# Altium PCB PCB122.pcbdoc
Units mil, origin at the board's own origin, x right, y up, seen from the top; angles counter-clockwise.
Board outline 8605 x 5800 mil, 2 copper layers (Top Layer, Bottom Layer); 37 components, 55 nets, 176 pads, 98 vias.
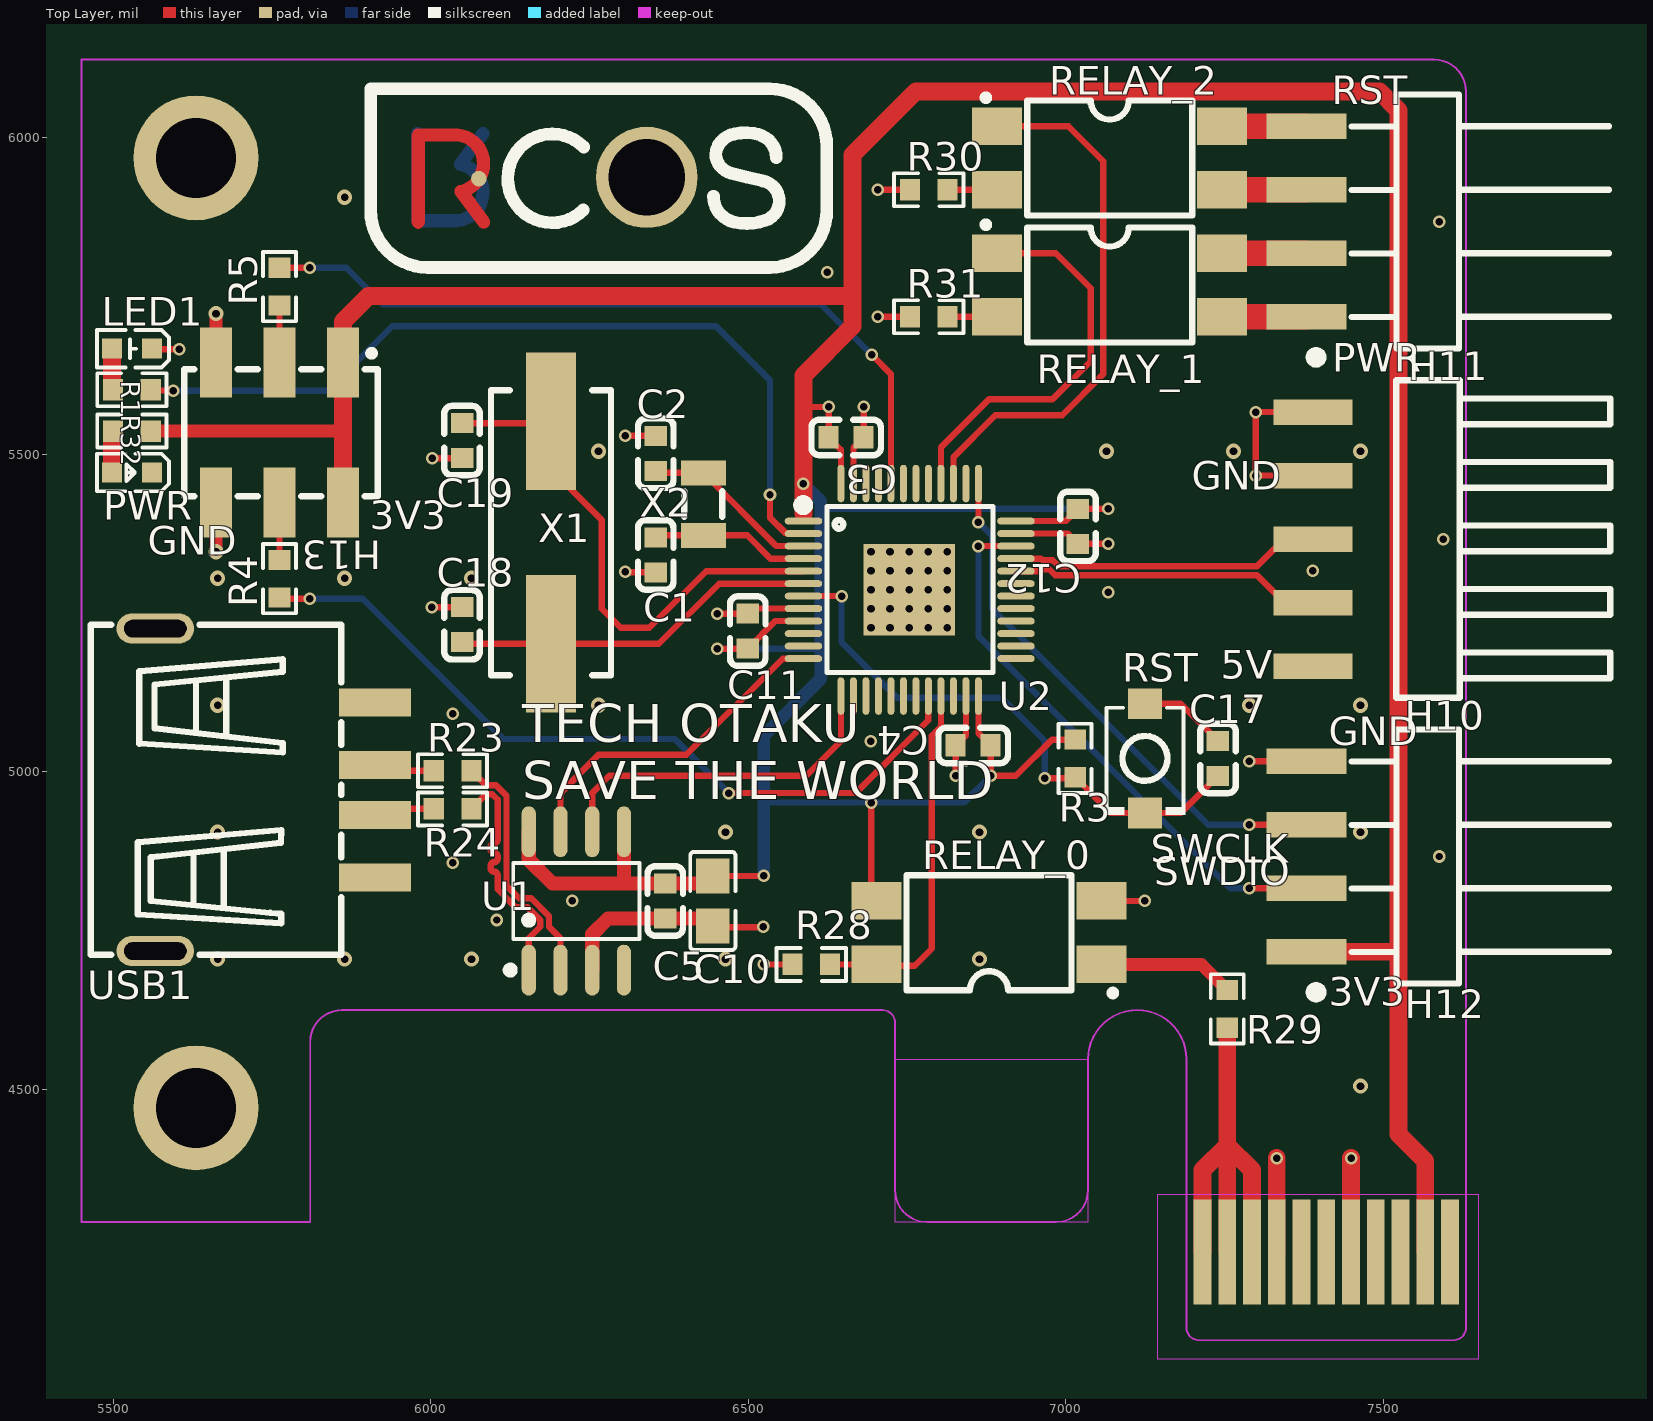
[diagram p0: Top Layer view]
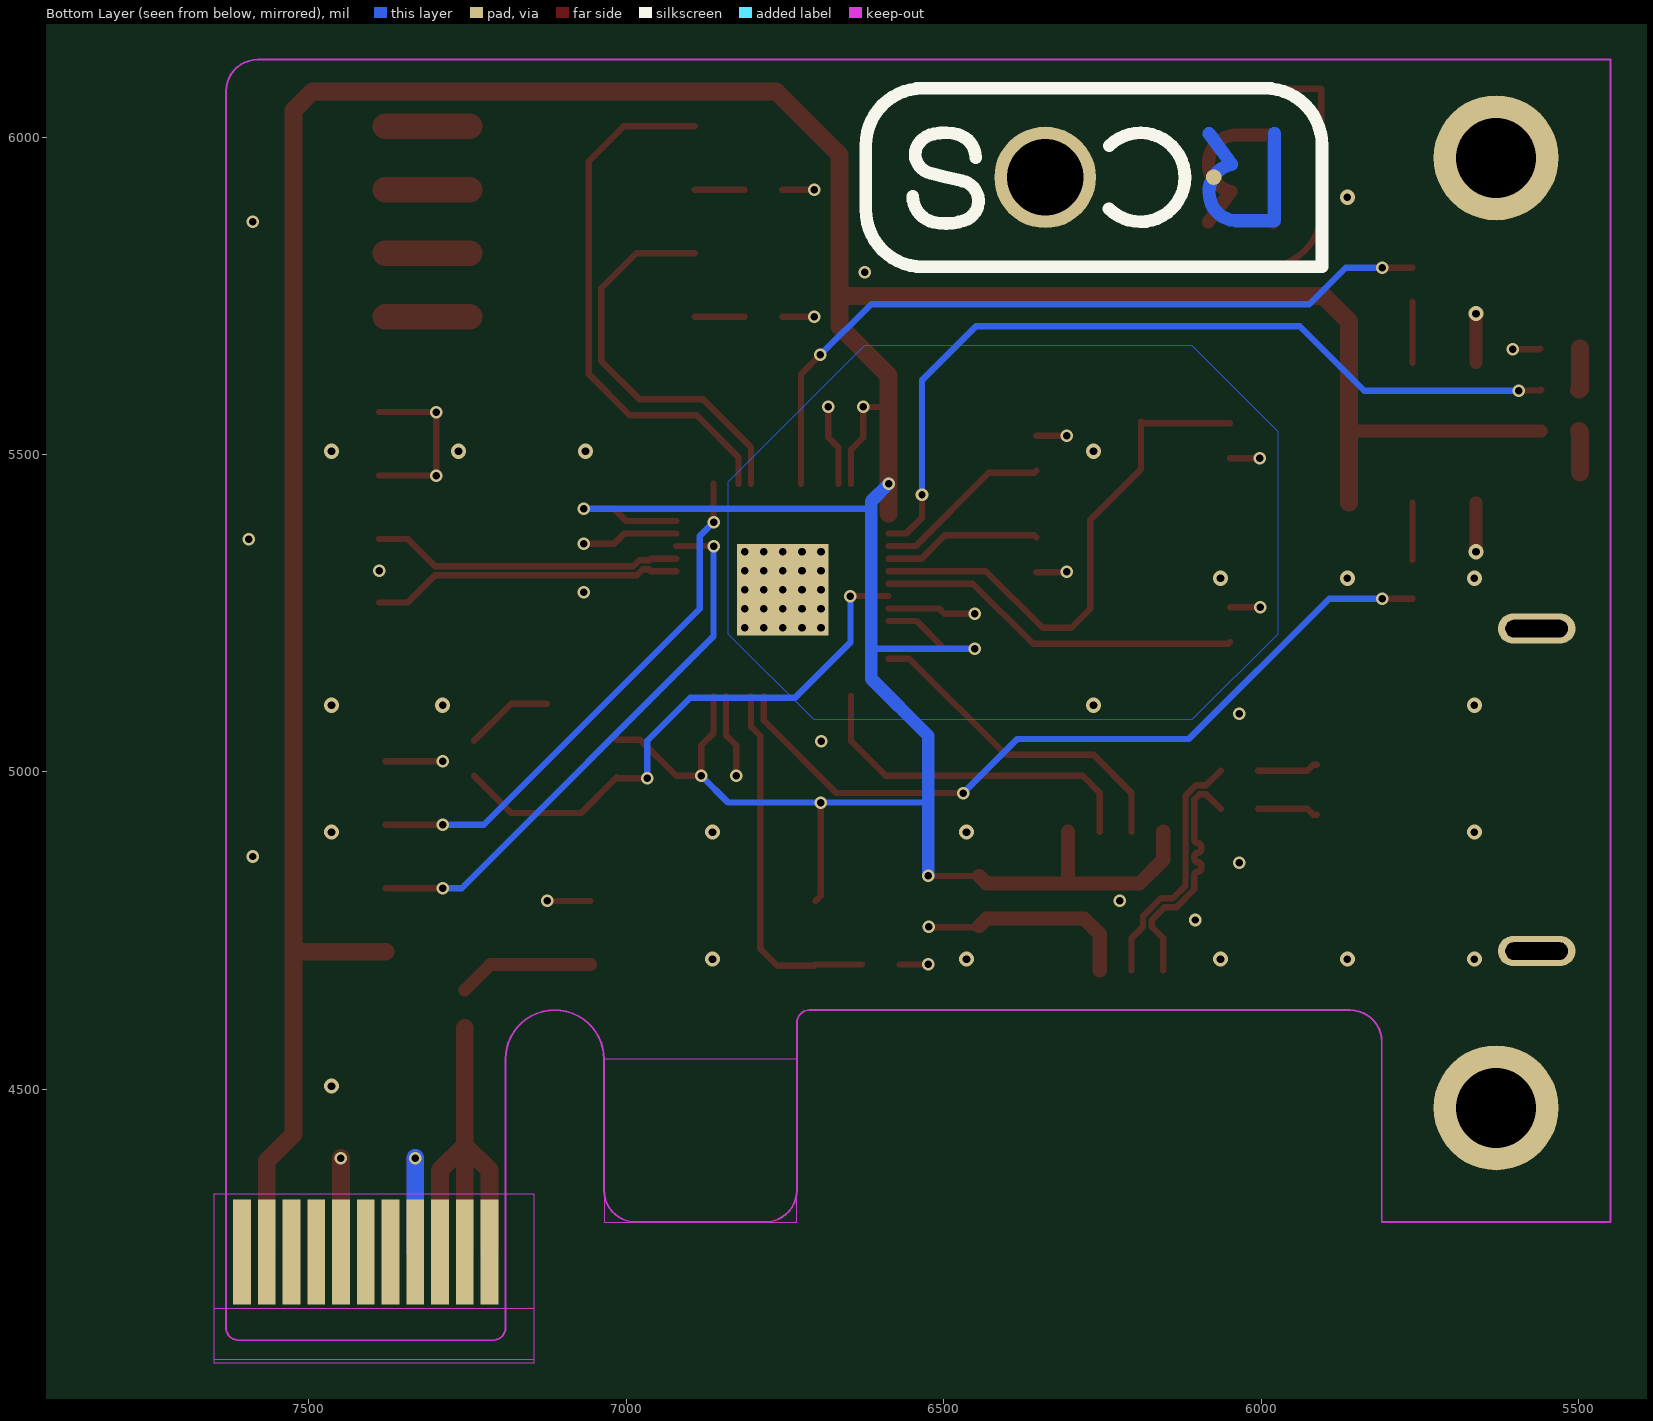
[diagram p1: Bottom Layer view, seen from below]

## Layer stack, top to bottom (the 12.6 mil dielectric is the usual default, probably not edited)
Top Layer: signal copper (thickness not stored)
Dielectric: dielectric 12.6, FR-4, Dk 4.8
Bottom Layer: signal copper (thickness not stored)

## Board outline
11355,2750 2750,2750 2750,8550 11355,8550

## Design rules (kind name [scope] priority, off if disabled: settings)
BoardOutlineClearance copperThickness1oz [All] p0: genericclearance=10 ignorepadtopadclearanceinfootprint=FALSE except(0: Arc-SplitContinuation Track-SplitContinuation SMDPad-SplitContinuation THPad-SplitContinuation Via-SplitContinuation Fill-SplitContinuation Poly-SplitContinuation Region-SplitContinuation Text-SplitContinuation; 6: SMDPad-CutoutEdge THPad-CutoutEdge Via-CutoutEdge Fill-CutoutEdge Region-CutoutEdge; 11: Track-OutlineEdge SMDPad-OutlineEdge THPad-OutlineEdge Via-OutlineEdge Fill-OutlineEdge Region-OutlineEdge Poly-OutlineEdge Text-OutlineEdge; 11.8: Track-CutoutEdge)
BoardOutlineClearance copperThickness2oz [All] p0: genericclearance=10 ignorepadtopadclearanceinfootprint=FALSE except(0: Arc-SplitContinuation Track-SplitContinuation SMDPad-SplitContinuation THPad-SplitContinuation Via-SplitContinuation Fill-SplitContinuation Poly-SplitContinuation Region-SplitContinuation Text-SplitContinuation; 6: SMDPad-CutoutEdge THPad-CutoutEdge Via-CutoutEdge Fill-CutoutEdge Region-CutoutEdge; 11.8: Track-OutlineEdge SMDPad-OutlineEdge THPad-OutlineEdge Via-OutlineEdge Fill-OutlineEdge Region-OutlineEdge Poly-OutlineEdge Text-OutlineEdge Track-CutoutEdge)
Clearance copperThickness1oz [(InNet('OSC32_OUT') OR InNet('GND') OR InNet('OSC32_IN') OR InNet('NRST') OR InNet('$1N1780') OR InNet('SWDIO') OR InNet('SWCLK') OR InNet('PA0') OR InNet('PA4') OR InNet('PA5') OR InNet('PA6') OR InNet('PA7') OR InNet('PB0') OR InNet('PB1') OR InNet('PB10') OR InNet('PB11') OR InNet('PB9') OR InNet('PB8') OR InNet('PB7') OR InNet('PB6') OR InNet('PB5') OR InNet('PB4') OR InNet('PB3') OR InNet('PA15') OR InNet('PA8') OR InNet('PB15') OR InNet('PB14') OR InNet('PB13') OR InNet('PB12') OR InNet('BOOT1') OR InNet('BOOT0') OR InNet('D-') OR InNet('DN') OR InNet('D+') OR InNet('DP') OR InNet('USBDM') OR InNet('USBDP') OR InNet('12V') OR InNet('3V3') OR InNet('UART2_RX') OR InNet('UART2_TX') OR InNet('RST_SW2') OR InNet('RST_SW1') OR InNet('PWR_SW2') OR InNet('PWR_SW1') OR InNet('$1N3179') OR InNet('$1N4269') OR InNet('$1N1798') OR InNet('$1N5301') OR InNet('$1N5302') OR InNet('OSC8_OUT') OR InNet('OSC8_IN') OR InNet('USE_LED') OR InNet('$1N5303') OR InNet('$1N7721'))] p1: gap=7 ignorepadtopadclearanceinfootprint=FALSE except(4: Track-Track; 6: Track-SMDPad SMDPad-SMDPad Track-THPad SMDPad-THPad THPad-THPad Track-Via SMDPad-Via THPad-Via Via-Via Track-Fill SMDPad-Fill THPad-Fill Via-Fill Fill-Fill SMDPad-Region THPad-Region Via-Region Fill-Region Region-Region Track-Poly SMDPad-Poly THPad-Poly Via-Poly Fill-Poly Poly-Poly Track-Text SMDPad-Text THPad-Text Via-Text Fill-Text Region-Text Poly-Text Text-Text; 6.9: Track-Hole SMDPad-Hole THPad-Hole Via-Hole Fill-Hole Region-Hole Poly-Hole Text-Hole Sheet-Hole; 11: Track-Sheet SMDPad-Sheet THPad-Sheet Via-Sheet Fill-Sheet Region-Sheet Poly-Sheet Text-Sheet; 11.8: Track-Region Region-Poly)
Clearance copperThickness2oz [All] p1: gap=7 ignorepadtopadclearanceinfootprint=FALSE except(6: Track-SMDPad SMDPad-SMDPad Track-THPad SMDPad-THPad THPad-THPad Track-Via SMDPad-Via THPad-Via Via-Via Track-Fill SMDPad-Fill THPad-Fill Via-Fill Fill-Fill SMDPad-Region THPad-Region Via-Region Fill-Region Region-Region Track-Poly SMDPad-Poly THPad-Poly Via-Poly Fill-Poly Poly-Poly Track-Text SMDPad-Text THPad-Text Via-Text Fill-Text Region-Text Poly-Text Text-Text; 6.9: Track-Hole SMDPad-Hole THPad-Hole Via-Hole Fill-Hole Region-Hole Poly-Hole Text-Hole Sheet-Hole; 8: Track-Track; 11.8: Track-Region Region-Poly Track-Sheet SMDPad-Sheet THPad-Sheet Via-Sheet Fill-Sheet Region-Sheet Poly-Sheet Text-Sheet)
DiffPairsRouting differentialPair [All] p1: maxuncoupledlength=10 minlimit=4 maxlimit=4 mostfreqgap=4 toplayer_minwidth=5 toplayer_prefwidth=10 toplayer_maxwidth=100 bottomlayer_minwidth=5 bottomlayer_prefwidth=10 bottomlayer_maxwidth=100
PasteMaskExpansion pasteMaskExpansion [All] p1: expansion=0
PlaneConnect innerPlane [All] p1: planeconnectstyle=Relief reliefexpansion=20 reliefentries=4 reliefconductorwidth=10 reliefairgap=10
PolygonConnect copperRegion [All] p1: connectstyle=Direct reliefentries=4 reliefconductorwidth=10 polygonreliefangle="90 Angle" airgapwidth=10
RoutingVias viaSize [All] p1: viastyle="Through Hole" holewidth=12 minholewidth=11.8 maxholewidth=248 width=24 minwidth=19.7 maxwidth=393.7
SolderMaskExpansion solderMaskExpansion [All] p1: useseparateexpansions=TRUE expansion=2 expansionbottom=2
Width copperThickness1oz [All] p1: maxlimit=100 minlimit=5 preferedwidth=10
Width copperThickness2oz [All] p1: maxlimit=100 minlimit=8 preferedwidth=10

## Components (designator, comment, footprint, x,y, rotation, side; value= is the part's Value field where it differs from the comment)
C1 "CL10C220JB8NNNC" C0603 6354.42,5341.92 r90 top
C2 "CL10C220JB8NNNC" C0603 6354.42,5501.92 r270 top
C3 "CGA0603X7R104K500JT" C0603 6654.42,5526.92 r180 top
C4 "CGA0603X7R104K500JT" C0603 6854.42,5041.92 r180 top
C5 "CGA0603X7R104K500JT" C0603 6369.42,4796.92 r90 top
C10 "CL21A106KAYNNNE_C15850" C0805 6444.42,4796.92 r90 top
C11 "CGA0603X7R104K500JT" C0603 6499.42,5221.92 r90 top
C12 "CGA0603X7R104K500JT" C0603 7019.42,5386.92 r270 top
C17 "CGA0603X7R104K500JT" C0603 7239.95,5021.39 r270 top
C18 "CL10C220JB8NNNC" C0603 6049.42,5231.92 r270 top
C19 "CL10C220JB8NNNC" C0603 6049.42,5521.92 r90 top
H10 "HX PZ2.54-1x5P WT" HDR-SMD_5P-P2.54-H-M-W12.8-N 7389.42,5366.92 r90 top
H11 "HX PZ2.54-1x4P WT" CONN-SMD_HX-PZ2.54-1X4P-WT 7379.42,5866.92 r90 top
H12 "HX PZ2.54-1x4P WT" CONN-SMD_HX-PZ2.54-1X4P-WT 7379.42,4866.92 r90 top
H13 "X6521WVS-2x03H-C60D74" HDR-SMD_6P-P2.54-V-M-R2-C5-S7.4 5761.92,5534.42 r180 top
LED1 "NCD0603G1" LED0603-RD_1 5529.42,5666.92 r180 top
PWR "XL-1608SURC-06" LED0603-RD_RED 5529.42,5471.92 r180 top
R1 "0603WAF1001T5E" R0603 5529.42,5601.92 r180 top
R3 "0603WAF1002T5E" R0603 7014.95,5021.39 r90 top
R4 "0603WAF1002T5E" R0603 5761.92,5304.42 r90 top
R5 "0603WAF1002T5E" R0603 5761.92,5764.42 r90 top
R23 "0603WAF220JT5E" R0603 6034.42,5001.92 r0 top
R24 "0603WAF220JT5E" R0603 6034.42,4941.92 r0 top
R28 "0603WAF1002T5E" R0603 6599.42,4696.92 r0 top
R29 "0603WAF2201T5E" R0603 7254.42,4626.92 r270 top
R30 "0603WAF4700T5E" R0603 6784.42,5916.92 r0 top
R31 "0603WAF4700T5E" R0603 6784.42,5716.92 r0 top
R32 "0603WAF1001T5E" R0603 5529.42,5536.92 r180 top
RELAY_0 "G3VM-61D1(TR)" SMD-4_L4.6-W6.4-P2.54-LS10.0-BL 6879.42,4746.92 r90 top
RELAY_1 "G3VM-61D1(TR)" SMD-4_L4.6-W6.4-P2.54-LS10.0-BL 7069.42,5766.92 r270 top
RELAY_2 "G3VM-61D1(TR)" SMD-4_L4.6-W6.4-P2.54-LS10.0-BL 7069.42,5966.92 r270 top
RST "TS-1088-AR02016" SW-SMD_L3.9-W3.0-P4.45 7124.95,5021.39 r270 top
U1 "CH340N_C506813" SOP-8_L5.0-W4.0-P1.27-LS6.0-BL 6229.42,4796.92 r0 top
U2 "STM32F103C8T6" STM32F103C8T6 6754.42,5286.92 r270 top
USB1 "10.0 QHHTZB6.3" USB-A-TH_10.0QHHTZB6.3 5739.42,4971.92 r270 top
X1 "X49SM8MSD2SC" CRYSTAL-SMD_L11.5-W4.8-LS12.7 6189.42,5376.92 r90 top
X2 "Q13FC13500004_C32346" FC-135R_L3.2-W1.5 6429.42,5421.92 r90 top

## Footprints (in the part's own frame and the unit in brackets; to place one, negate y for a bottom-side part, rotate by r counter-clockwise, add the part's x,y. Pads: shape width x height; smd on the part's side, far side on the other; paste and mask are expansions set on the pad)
C0603 [mm]
  rect 0.8x0.9 smd: 1(-0.7,0) 2(0.7,0)
  silkscreen extent -1.39,-0.71 1.39,0.71
C0805 [mm]
  rect 1.41x1.35 smd: 1(-1,0) 2(1,0)
  silkscreen extent -1.96,-0.9 1.96,0.9
CONN-SMD_HX-PZ2.54-1X4P-WT [mm]
  rect 1.02x3.2 smd: 1(-3.81,0) 2(-1.27,0) 3(1.27,0) 4(3.81,0)
  silkscreen extent -5.84,-12.1 5.08,0.03
CRYSTAL-SMD_L11.5-W4.8-LS12.7 [mm]
  rect 5.5x2 smd: 1(-4.45,0) 2(4.45,0)
  silkscreen extent -5.7,-2.4 5.7,2.4
FC-135R_L3.2-W1.5 [mm]
  rect 1x1.8 smd: 1(-1.25,0) 2(1.25,0)
  silkscreen extent -0.51,-0.76 0.51,0.76
HDR-SMD_5P-P2.54-H-M-W12.8-N [mm]
  rect 1.02x3.17 smd: 1(-5.08,0) 2(-2.54,0) 3(0,0) 4(2.54,0) 5(5.08,0)
  silkscreen extent -6.35,-11.9 6.35,-3.33
HDR-SMD_6P-P2.54-V-M-R2-C5-S7.4 [mm]
  rect 1.27x2.8 smd: 1(-2.54,-2.8) 2(-2.54,2.8) 3(0,-2.8) 4(0,2.8) 5(2.54,-2.8) 6(2.54,2.8)
  silkscreen extent -3.94,-3.3 3.81,2.54
LED0603-RD_1 [mm]
  rect 0.8x0.8 smd: 1(-0.799,-0.004) 2(0.799,0.004)
  silkscreen extent -1.49,-0.75 1.39,0.76
LED0603-RD_RED [mm]
  rect 0.8x0.8 smd: 1(-0.8,-0.003) 2(0.8,0.003)
  silkscreen extent -1.49,-0.75 1.39,0.76
R0603 [mil]
  rect 31.75x34.02 smd: 1(-29.66,0) 2(29.66,0)
  silkscreen extent -55,-26 55,26
SMD-4_L4.6-W6.4-P2.54-LS10.0-BL [mm]
  rect 1.5x2 smd: 1(-1.27,-4.5) 2(1.27,-4.5) 3(1.27,4.5) 4(-1.27,4.5)
  silkscreen extent -2.54,-5.08 2.3,3.3
SOP-8_L5.0-W4.0-P1.27-LS6.0-BL [mil]
  oval 22.6x80.14 smd: 1(-75,-108.97) 2(-25,-108.97) 3(25,-108.97) 4(75,-108.97) 5(75,108.97) 6(25,108.97) 7(-25,108.97) 8(-75,108.97)
  silkscreen extent -110,-115 99,60
STM32F103C8T6 [mil]
  oval 10.6x59.1 smd: 1(-108.3,-167.3) 2(-88.6,-167.3) 3(-68.9,-167.3) 4(-49.2,-167.3) 5(-29.5,-167.3) 6(-9.8,-167.3) 7(9.8,-167.3) 8(29.5,-167.3) 9(49.2,-167.3) 10(68.9,-167.3) 11(88.6,-167.3) 12(108.3,-167.3) 25(108.3,167.3) 26(88.6,167.3) 27(68.9,167.3) 28(49.2,167.3) 29(29.5,167.3) 30(9.8,167.3) 31(-9.8,167.3) 32(-29.5,167.3) 33(-49.2,167.3) 34(-68.9,167.3) 35(-88.6,167.3) 36(-108.3,167.3)
  oval 59.1x10.6 smd: 13(167.3,-108.3) 14(167.3,-88.6) 15(167.3,-68.9) 16(167.3,-49.2) 17(167.3,-29.5) 18(167.3,-9.8) 19(167.3,9.8) 20(167.3,29.5) 21(167.3,49.2) 22(167.3,68.9) 23(167.3,88.6) 24(167.3,108.3) 37(-167.3,108.3) 38(-167.3,88.6) 39(-167.3,68.9) 40(-167.3,49.2) 41(-167.3,29.5) 42(-167.3,9.8) 43(-167.3,-9.8) 44(-167.3,-29.5) 45(-167.3,-49.2) 46(-167.3,-68.9) 47(-167.3,-88.6) 48(-167.3,-108.3)
  silkscreen extent -141,-176 130,132
SW-SMD_L3.9-W3.0-P4.45 [mm]
  rect 1.23x1.36 smd: 1(-2.185,0) 2(2.185,0)
  silkscreen extent -2.03,-1.62 2.25,1.62
USB-A-TH_10.0QHHTZB6.3 [mm]
  rect 1.12x2.88 smd: 1(-3.5,4.395) 2(-1,4.395) 3(1,4.395) 4(3.5,4.395)
  oval 1.2x3.1 hole 0.7 slot 2.5 at 90 deg: 5(-6.45,-4.395) 6(6.45,-4.395)
  silkscreen extent -6.6,-6.99 6.6,3.05

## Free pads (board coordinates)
  round 196.85 hole 125.98: 1(5630.3,4471.2) 2(5630.29,5967.27)
  round 160 hole 120: 1(6340.42,5936.54)
  round 24.6 smd far side: 2(6074.93,5936.96)
  round 24.6 smd: 2(6075.93,5934.5)
  rect 144x144 smd far side: 2(6753.44,5286.92)
  rect 144x144 smd: 2(6753.44,5286.92)
  rect 28x165 smd far side: A1(7215.45,4244) A2(7254.45,4244) A3(7293.45,4244) A4(7332.45,4244) A5(7371.45,4244) A6(7410.45,4244) A7(7449.45,4244) A8(7488.45,4244) A9(7527.45,4244) A10(7566.45,4244) A11(7605.45,4244)
  rect 28x165 smd: B1(7215.45,4244) B2(7254.45,4244) B3(7293.45,4244) B4(7332.45,4244) B5(7371.45,4244) B6(7410.45,4244) B7(7449.45,4244) B8(7488.45,4244) B9(7527.45,4244) B10(7566.45,4244) B11(7605.45,4244)

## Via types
v1: diameter 19.7, hole 11.8, Top Layer to Bottom Layer, 49 vias
v2: diameter 24, hole 12, Top Layer to Bottom Layer, 49 vias

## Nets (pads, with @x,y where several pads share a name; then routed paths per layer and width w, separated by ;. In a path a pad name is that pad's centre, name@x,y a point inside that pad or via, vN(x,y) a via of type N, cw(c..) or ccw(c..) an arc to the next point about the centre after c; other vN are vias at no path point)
3V3: C3.2 C4.1 C5.2 C10.2 C11.1 C12.1 H12.1 H13.1 H13.2 pad.B10 R3.2 R32.1 RELAY_0.3 U1.5 U1.8 U2.1 U2.9 U2.24 U2.36 U2.48 | length 7973
  Top Layer w10: C10.2 6523.79,4836.29 v1(6524.42,4836.92) ; v1(6451.42,5194.36) C11.1 6542.78,5237.72 U2.9 ; 6587.12,5574.99 6587.2,5574.92 v1(6626.86,5574.92) C3.2 6646.12,5507.66 U2.48 ; v1(6693.86,4951.92) 6693.86,4805.31 RELAY_0.3 ; U2.24 6862.72,5061.18 C4.1 v1(6881.98,4993.92) 6921.42,4993.92 6978.55,5051.05 R3.2 ; U2.36 7000.16,5395.22 C12.1 v1(7067.42,5414.48)
  Top Layer w20: R32.1 5861.04,5536.92 5861.92,5537.8
  Top Layer w22.6: U1.8 6154.42,4861.92 6191.86,4824.48 C5.2 6432.61,4824.48 C10.2 ; 6304.42,4824.95 U1.5
  Top Layer w28: H13.2 5861.92,5537.8 H13.1 5861.92,5709.42 5902.12,5749.62 6663.74,5749.62 ; 6587.12,5406.92 v1(6587.12,5453.78) 6587.12,5624.62 6664.42,5701.92 6664.42,5971.92 6764.42,6071.92 7494.42,6071.92 7524.42,6041.92 7524.42,4429.55 7566.45,4387.52 pad.B10 ; H12.1 7521.15,4716.62
  Bottom Layer w10: v1(6451.42,5194.36) 6614.35,5194.36 6614.42,5194.29 ; 6524.42,4949.59 6526.75,4951.92 v1(6693.86,4951.92) 6839.98,4951.92 v1(6881.98,4993.92) ; 6614.42,5416.08 6616.02,5414.48 v1(7067.42,5414.48)
  Bottom Layer w20: v1(6524.42,4836.92) 6524.42,5056.92 6614.42,5146.92 6614.42,5416.08 6614.42,5426.48 v1(6587.12,5453.78)
12V: pad.B1 pad.B2 pad.B3 R29.2 | length 722
  Top Layer w28: pad.B1 7215.45,4373.23 7254.45,4412.23 ; pad.B2 7254.45,4412.23 ; R29.2@7254.45,4597.23 7254.45,4412.23 ; pad.B3 7293.45,4373.23 7254.45,4412.23
$1N1780: H13.4 R4.2 | length 90.1
  Top Layer w10: R4.2 H13.4
$1N1798: U2.11
$1N3179: H13.3 R5.1 | length 95.1
  Top Layer w10: H13.3 R5.1@5761.92,5739.76
$1N4269: LED1.2 R1.2 | length 65.6
  Top Layer w28: LED1.2 5497.94,5603.73 R1.2
$1N5301: R30.2 RELAY_2.2 | length 78.2
  Top Layer w10: R30.2 RELAY_2.2
$1N5302: R31.2 RELAY_1.2 | length 78.2
  Top Layer w10: R31.2 RELAY_1.2
$1N5303: R29.1 RELAY_0.1 | length 214.5
  Top Layer w20: RELAY_0.1 7214.08,4696.92 R29.1
$1N7721: PWR.2 R32.2 | length 65.9
  Top Layer w28: PWR.2 5497.94,5535.1 R32.2
BOOT0: R5.2 U2.44 | length 1204.6
  Top Layer w10: R5.2 v1(5809.92,5794.08) ; v1(6694.42,5656.92) 6724.92,5626.42 U2.44
  Bottom Layer w10: v1(5809.92,5794.08) 5867.26,5794.08 5924.42,5736.92 6614.42,5736.92 v1(6694.42,5656.92)
BOOT1: R4.1 U2.20 | length 1234.5
  Top Layer w10: R4.1@5761.92,5273.12 v1(5809.92,5273.12) ; v1(6469.42,4966.92) 6669.42,4966.92 6783.92,5081.42 U2.20
  Bottom Layer w10: v1(5809.92,5273.12) 5893.22,5273.12 6114.42,5051.92 6384.42,5051.92 v1(6469.42,4966.92)
D+: R24.2 U1.1 | length 394.3
  Top Layer w10: R24.2 6087.08,4964.92 6097.08,4964.92 6105.42,4956.58 6105.42,4893.46 cw(c6099.92,4893.46) 6099.92,4887.96 ccw(c6099.92,4882.46) 6094.42,4882.46 6094.42,4878.46 ccw(c6099.92,4878.46) 6099.92,4872.96 cw(c6099.92,4867.46) 6105.42,4867.46 6105.42,4863.46 cw(c6099.92,4863.46) 6099.92,4857.96 ccw(c6099.92,4852.46) 6094.42,4852.46 6094.42,4848.46 ccw(c6099.92,4848.46) 6099.92,4842.96 cw(c6099.92,4837.46) 6105.42,4837.46 6105.42,4815.12 6133.62,4786.92 6152.42,4786.92 6172.42,4766.92 6172.42,4756.01 6154.42,4738.01 U1.1
D-: R23.2 U1.2 | length 392.4
  Top Layer w10: R23.2 6087.08,4978.92 6102.88,4978.92 6119.42,4962.37 6119.42,4820.92 6139.42,4800.92 6158.22,4800.92 6186.42,4772.71 6186.42,4756.01 6204.42,4738.01 U1.2
DN: R23.1 USB1.2 | length 96.2
  Top Layer w10: USB1.2 5918.25,5011.29 5927.62,5001.92 R23.1
DP: R24.1 USB1.3 | length 96.2
  Top Layer w10: USB1.3 5918.25,4932.55 5927.62,4941.92 R24.1
GND: C1.1 C2.1 C3.1 C4.2 C5.1 C10.1 C11.2 C12.2 C17.1 C18.1 C19.1 H10.4 H10.5 H12.4 H13.5 H13.6 LED1.1 pad.2@6753.44,5286.92 pad.A4 pad.B4 pad.B7 PWR.1 R28.1 R30.1 R31.1 RELAY_0.2 RST.1 U1.3 U2.8 U2.23 U2.35 U2.47 USB1.4 | length 2449.1
  Top Layer w10: LED1.1 5562.31,5665.65 v1(5604.25,5665.65) ; v1(6001.46,5259.48) C18.1 ; v1(6002.46,5494.14) 6002.68,5494.36 C19.1 ; v1(6306.46,5315.14) 6307.24,5314.36 C1.1 ; v1(6306.46,5529.48) C2.1 ; C10.1@6443.63,4755.67 6523,4755.67 v1(6523.63,4756.3) ; v1(6451.42,5249.48) C11.2 6507.36,5257.42 U2.8 ; v1(6524.85,4696.92) R28.1 ; U2.47 6665.82,5510.76 C3.1 v1(6681.98,5574.92) ; v1(6704.42,5716.91) R31.1 ; v1(6704.42,5916.92) R30.1 ; v1(6826.86,4993.92) C4.2 6843.02,5058.08 U2.23 ; U2.35 7003.26,5375.52 C12.2 v1(7067.42,5359.36) ; RELAY_0.2 v1(7124.42,4796.92) ; RST.1 7181.49,5107.41 C17.1 ; v1(7289.42,5016.92) H12.4 ; H10.4 v1(7299.42,5466.92) v1(7299.42,5566.92) H10.5
  Top Layer w20: v2(5661.92,5346.92) H13.6 ; H13.5 v2(5661.92,5721.92)
  Top Layer w22.6: U1.3 6254.42,4744.36 6279.42,4769.36 C5.1 6432.61,4769.36 C10.1
  Top Layer w28: pad.B4 v1(7332.45,4391.92) ; pad.B7 v1(7449.45,4391.88)
  Bottom Layer w28: pad.A4 v1(7332.45,4391.92)
  other v1: 6104.42,4766.92 6222.69,4796.92 6034.42,4856.92 7588.61,4866.92 6692.85,5048.62 6034.42,5091.92 7067.42,5283.38 7389.42,5316.92 7594.97,5366.92 6624.42,5786.92 7588.61,5866.92
  other v2: 7464.4,4505.3 5664.4,4705.3 5864.4,4705.3 6064.4,4705.3 6464.4,4705.3 6864.4,4705.3 5664.4,4905.3 6464.4,4905.3 6864.4,4905.3 7464.4,4905.3 5664.4,5105.3 6264.4,5105.3 7289.4,5105.3 7464.4,5105.3 6693.44,5226.92 6723.44,5226.92 6753.44,5226.92 6783.44,5226.92 6813.44,5226.92 6693.44,5256.92 6723.44,5256.92 6753.44,5256.92 6783.44,5256.92 6813.44,5256.92 6693.44,5286.92 6723.44,5286.92 6753.44,5286.92 6783.44,5286.92 6813.44,5286.92 5664.4,5305.3 5864.4,5305.3 6064.4,5305.3 6693.44,5316.92 6723.44,5316.92 6753.44,5316.92 6783.44,5316.92 6813.44,5316.92 6693.44,5346.92 6723.44,5346.92 6753.44,5346.92 6783.44,5346.92 6813.44,5346.92 6264.4,5505.3 7064.4,5505.3 7264.4,5505.3 7464.4,5505.3 5864.4,5905.3
NRST: C17.2 R3.1 RST.2 U2.7 | length 897.4
  Top Layer w10: U2.7 v1(6647.12,5277.12) ; v1(6966.94,4990.09) 7013.31,4990.09 R3.1 7071.31,4935.37 RST.2 7181.49,4935.37 C17.2
  Bottom Layer w10: v1(6647.12,5277.12) 6647.12,5204.22 6734.42,5116.92 6899.42,5116.92 6966.94,5049.39 v1(6966.94,4990.09)
OSC8_IN: C19.2 U2.5 X1.2 | length 836.6
  Top Layer w10: C19.2 6186.78,5549.48 X1.2 6189.42,5476.92 6269.42,5396.92 6269.42,5256.92 6299.42,5226.92 6344.42,5226.92 6433.92,5316.42 U2.5
OSC8_OUT: C18.2 U2.6 X1.1 | length 578.1
  Top Layer w10: C18.2 6052.06,5201.72 X1.1 6359.22,5201.72 6454.22,5296.72 U2.6
OSC32_IN: C2.2 U2.3 X2.2 | length 281.8
  Top Layer w10: C2.2 6357.64,5471.13 X2.2 6544.74,5355.82 U2.3
OSC32_OUT: C1.2 U2.4 X2.1 | length 249.2
  Top Layer w10: C1.2 6357.64,5372.7 X2.1 6498.63,5372.7 6535.22,5336.12 U2.4
PA0: U2.10
PA4: U2.14
PA5: U2.15
PA6: U2.16
PA7: U2.17
PA8: U2.29
PA15: U2.38
PB0: U2.18
PB1: U2.19
PB3: RELAY_2.1 U2.39 | length 857
  Top Layer w10: U2.39 6823.32,5495.82 6889.42,5561.92 6994.42,5561.92 7059.42,5626.92 7059.42,5961.92 7004.42,6016.92 RELAY_2.1
PB4: RELAY_1.1 U2.40 | length 633.9
  Top Layer w10: U2.40 6803.62,5511.12 6879.42,5586.92 6979.42,5586.92 7039.42,5646.92 7039.42,5761.92 6984.42,5816.92 RELAY_1.1
PB5: U2.41
PB6: U2.42
PB7: U2.43
PB8: U2.45
PB9: U2.46
PB10: R28.2 RELAY_0.4 U2.21 | length 576
  Top Layer w10: R28.2 RELAY_0.4 6704.32,4694.84 6762.35,4694.84 6789.42,4721.92 6789.42,5056.92 6803.62,5071.12 U2.21
PB11: U2.22
PB12: U2.25
PB13: U2.26
PB14: U2.27
PB15: U2.28
PWR_SW1: H11.4 RELAY_2.4 | length 132.8
  Top Layer w40.2: RELAY_2.4 H11.4
PWR_SW2: H11.3 RELAY_2.3 | length 132.8
  Top Layer w40.2: RELAY_2.3 H11.3
RST_SW1: H11.2 RELAY_1.4 | length 132.8
  Top Layer w40.2: RELAY_1.4 H11.2
RST_SW2: H11.1 RELAY_1.3 | length 132.8
  Top Layer w40.2: RELAY_1.3 H11.1
SWCLK: H12.3 U2.37 | length 842.1
  Top Layer w10: v1(6862.72,5393.47) U2.37 ; v1(7289.42,4916.92) H12.3
  Bottom Layer w10: v1(6862.72,5393.47) 6884.42,5371.77 6884.42,5256.92 7224.42,4916.92 v1(7289.42,4916.92)
SWDIO: H12.2 U2.34 | length 882.2
  Top Layer w10: v1(6862.72,5355.82) U2.34 ; v1(7289.42,4816.92) H12.2
  Bottom Layer w10: v1(6862.72,5355.82) 6862.72,5213.62 7259.42,4816.92 v1(7289.42,4816.92)
UART2_RX: U1.6 U2.13 | length 557.6
  Top Layer w10: U1.6 6254.42,4966.92 6281.49,4993.99 6591.49,4993.99 6646.12,5048.62 U2.13
UART2_TX: U1.7 U2.12 | length 531.4
  Top Layer w10: U1.7 6204.42,4966.92 6264.42,5026.92 6402.72,5026.92 6554.42,5178.62 U2.12
USBDM: H10.2 U2.32 | length 490.6
  Top Layer w10: U2.32 6961.27,5316.42 6964.12,5319.27 6974.12,5319.27 6983.47,5309.92 7301.42,5309.92 7344.42,5266.92 H10.2
USBDP: H10.3 U2.33 | length 490.6
  Top Layer w10: U2.33 6961.27,5336.12 6964.12,5333.27 6979.92,5333.27 6989.27,5323.92 7301.42,5323.92 7344.42,5366.92 H10.3
USE_LED: R1.1 U2.2 | length 1332.5
  Top Layer w10: R1.1 5560.19,5600.81 5593.96,5600.81 v1(5594.27,5600.5) ; v1(6534.42,5436.92) 6534.42,5400.61 6559.52,5375.52 U2.2
  Bottom Layer w10: v1(5594.27,5600.5) 5838.01,5600.5 5939.42,5701.92 6449.42,5701.92 6534.42,5616.92 v1(6534.42,5436.92)
pads on no net: H10.1 U1.4 U2.30 U2.31 USB1.1 USB1.5 USB1.6
copper on no net: | length 1883.9
  Top Layer w10: 5905.42,5884.54 5905.42,6075.92 6533.92,6075.92 cw(c6533.92,5985.92) 6623.92,5985.92 6623.92,5884.54 cw(c6533.92,5884.54) 6533.92,5794.54 5995.42,5794.54 cw(c5995.42,5884.54) 5905.42,5884.54

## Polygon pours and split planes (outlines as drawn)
3V3 on Top Layer (solid, remove dead copper, pour order 0): 6572.92,5407.92 6601.42,5407.92 6601.42,5395.22 6572.92,5395.22
GND on Bottom Layer (solid, remove dead copper, pour order 6): 3685,6825 10020,6825 10020,3595 3685,3595
GND on Top Layer (solid, remove dead copper, pour order 2): 3000,8300 11105,8300 11105,3000 3000,3000
GND on Bottom Layer (solid, remove dead copper, pour order 4): 6109.42,5081.92 6704.42,5081.92 6839.42,5216.92 6839.42,5456.92 6624.42,5671.92 6109.42,5671.92 5974.42,5536.92 5974.42,5216.92

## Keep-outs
Top Layer:
  region: 5905.42,5884.54 5905.42,6075.92 6533.92,6075.92 cw(c6533.92,5985.92) 6623.92,5985.92 6623.92,5884.54 cw(c6533.92,5884.54) 6533.92,5794.54 5995.42,5794.54 cw(c5995.42,5884.54)
Bottom Layer:
  region: 7145,4155 7650,4155 7650,4070 7145,4070
Board Outline Layer:
  region: 6731.5,4547.41 7035.11,4547.41 7035.11,4291.2 6731.5,4291.2
  region: 7145,4335 7650,4335 7650,4075 7145,4075
  lines w3: 5450.3,4291.2 5810.3,4291.2 5810.3,4575 cw(c5860.3,4575) 5860.3,4625 6711.5,4625 cw(c6711.5,4605) 6731.5,4605 6731.5,4341.2 ccw(c6781.5,4341.2) 6781.5,4291.2 6985.15,4291.2 ccw(c6985.15,4341.2) 7035.15,4341.2 7035.15,4547.4 cw(c7112.8,4547.4) 7190.45,4547.4 7190.41,4125 ccw(c7210.41,4125) 7210.41,4105 7610.5,4105 ccw(c7610.5,4125) 7630.5,4125 7630.52,6071.92 ccw(c7580.52,6071.92) 7580.52,6121.92 5450.3,6121.92 5450.3,4291.2

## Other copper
Top Layer:
  region: 5980.42,5855.83 cw(c5980.42,5865.83) 5970.42,5865.83 5970.42,6003.17 cw(c5980.42,6003.17) 5980.42,6013.17 6043.15,6013.17 cw(c6043.15,6003.17) 6044.51,6013.07 cw(c6038.41,5958.43) 6093.4,5958.43 cw(c6038.41,5958.43) 6063.69,5909.59 6091.47,5871.84 cw(c6083.42,5865.92) 6093.42,5865.92 cw(c6083.42,5865.92) 6083.42,5855.92 cw(c6083.42,5865.92) 6075.37,5859.99 6039.67,5908.49 cw(c6047.72,5914.42) 6037.72,5914.42 cw(c6047.72,5914.42) 6045.65,5924.2 ccw(c6038.41,5958.43) 6073.4,5958.43 ccw(c6038.41,5958.43) 6042.56,5993.17 5990.42,5993.17 5990.42,5865.83 cw(c5980.42,5865.83)
Bottom Layer:
  region: 5979.42,6015.63 cw(c5979.42,6005.63) 5989.42,6005.63 5989.42,5878.29 6041.56,5878.29 ccw(c6037.41,5913.03) 6072.4,5913.03 ccw(c6037.41,5913.03) 6044.65,5947.26 cw(c6046.72,5957.04) 6036.72,5957.04 cw(c6046.72,5957.04) 6038.67,5962.97 6074.37,6011.47 cw(c6082.42,6005.54) 6082.42,6015.54 cw(c6082.42,6005.54) 6092.42,6005.54 cw(c6082.42,6005.54) 6090.47,5999.62 6062.69,5961.87 cw(c6037.41,5913.03) 6092.4,5913.03 cw(c6037.41,5913.03) 6043.51,5858.39 cw(c6042.15,5868.29) 6042.15,5858.29 5979.42,5858.29 cw(c5979.42,5868.29) 5969.42,5868.29 5969.42,6005.63 cw(c5979.42,6005.63)

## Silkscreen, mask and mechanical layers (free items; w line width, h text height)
Top Silkscreen Layer:
  lines w20: 6240.45,5885.05 cw(c6191.32,5934.92) 6240.88,5984.35 ; 6445.42,5906.92 ccw(c6487.39,5906.92) 6478.42,5865.92 ccw(c6497.63,5953.74) 6527.42,5868.92 ccw(c6516.74,5899.33) 6546.42,5911.92 ccw(c6516.64,5899.29) 6523.42,5930.92 cw(c6743.7,6958.9) 6473.42,5942.92 cw(c6482,5975.17) 6449.42,5967.92 cw(c6479.46,5972.17) 6456.42,5991.92 cw(c6486.48,5966.16) 6478.42,6004.92 cw(c6496.3,5918.92) 6508.42,6005.92 cw(c6501.86,5958.83) 6527.42,5998.92 cw(c6507.66,5967.92) 6544.42,5967.92 ; 5905.42,5884.54 5905.42,6075.92 6533.92,6075.92 cw(c6533.92,5985.92) 6623.92,5985.92 6623.92,5884.54 cw(c6533.92,5884.54) 6533.92,5794.54 5995.42,5794.54 cw(c5995.42,5884.54) 5905.42,5884.54
  text "RST" at 7419.42,6051.92 h45
  text "PWR" at 7419.77,5630.59 h45
  text "GND" at 7198.37,5444.42 h45
  text "3V3" at 5904.42,5381.92 h45
  text "GND" at 5554.42,5341.92 h45
  text "5V" at 7244.42,5146.92 h45
  text "GND" at 7414.42,5041.92 h45
  text "TECH OTAKU / SAVE THE WORLD" at 6144.42,4956.92 h60
  text "SWCLK" at 7134.42,4856.92 h45
  text "SWDIO" at 7139.42,4821.92 h45
  text "3V3" at 7414.42,4631.92 h45
Bottom Silkscreen Layer:
  lines w20: 6239.45,5986.41 ccw(c6190.32,5936.54) 6239.88,5887.11 ; 6449.98,5967.92 cw(c6486.74,5967.92) 6466.98,5998.92 cw(c6492.54,5958.83) 6485.98,6005.92 cw(c6498.09,5918.92) 6515.98,6004.92 cw(c6507.92,5966.16) 6537.98,5991.92 cw(c6514.94,5972.17) 6544.98,5967.92 cw(c6512.4,5975.17) 6520.98,5942.92 cw(c6250.7,6958.9) 6470.98,5930.92 ccw(c6477.75,5899.29) 6447.98,5911.92 ccw(c6477.66,5899.33) 6466.98,5868.92 ccw(c6496.76,5953.74) 6515.98,5865.92 ccw(c6507.01,5906.92) 6548.98,5906.92 ; 5904.42,5795.54 5904.42,5986.92 cw(c5994.42,5986.92) 5994.42,6076.92 6532.92,6076.92 cw(c6532.92,5986.92) 6622.92,5986.92 6622.92,5885.54 cw(c6532.92,5885.54) 6532.92,5795.54 5904.42,5795.54
Top Solder Mask Layer:
  region: 6731.46,4537.41 7035.07,4537.41 7035.07,4291.2 6731.46,4291.2
  region: 7145,4330 7665,4330 7665,4070 7145,4070
Bottom Solder Mask Layer:
  region: 6731.54,4537.4 7035.15,4537.4 7035.15,4291.19 6731.54,4291.19
  region: 7145,4330 7665,4330 7665,4070 7145,4070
